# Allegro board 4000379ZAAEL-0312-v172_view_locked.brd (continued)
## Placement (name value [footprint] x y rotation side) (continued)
R937  4.7 K  [R0603]  62.29 85.85 180 top
R938  1 K/1%  [R0402]  131.32 21.11 270 top
R939  4.7 K  [R0603]  84.84 77.15 270 top
R940  4.7 K  [R0603]  104.46 101.54 90 top
R941  1 K/1%  [R0402]  132.46 21.11 90 top
R949  10 K  [R0402]  112.97 58.29 270 bottom
R951  49.9 OHM/1%  [R0402]  123.69 21.78 180 bottom
R955  22 OHM  [R0402]  138.05 50.61 180 top
R956  0 OHM  [R0402]  137.41 55.37 0 top
R958  10 K  [R0402]  137.67 49.21 90 top
R963  0 OHM  [R0402]  111.51 58.04 0 bottom
R975  0 OHM  [R0402]  114.68 58.1 180 bottom
R976  10 K/5%  [R0402]  133.77 51.09 90 top
R977  13 K/1%  [R0402]  133.77 49.19 90 top
R978  10 K/5%  [R0402]  133.77 55.38 90 top
R979  13 K/1%  [R0402]  133.77 53.48 90 top
R980  4.7 K  [R0603]  109.54 56.39 270 bottom
R983  16 K/1%  [R0402]  128.27 50.99 90 top
R984  20 K/1%  [R0402]  128.27 49.15 90 top
R985  220 K  [R0402]  34.54 149.92 180 top
R986  0 OHM  [R0402]  40.26 12.76 90 top
R987  0 OHM  [R0402]  35.12 12.76 90 top
R988  0 OHM  [R0402]  83.06 12.76 90 top
R989  0 OHM  [R0402]  77.98 12.76 90 top
R990  0 OHM  [R0402]  51.5 12.76 90 top
R991  0 OHM  [R0805]  29.21 152.27 0 top
R992  1 K  [R0402]  39.69 156.91 180 top
R993  0.01 OHM  [R1206]  39.69 158.62 180 top
R994  0.02 OHM  [R1206]  12.19 54.1 180 top
R995  68 K  [R0402]  36.39 149.92 0 top
R996  5.1 K  [R0402]  28.45 154.94 180 top
R997  5.1 K  [R0402]  30.29 154.94 0 top
R998  1.2 K  [R0402]  36.77 151.57 270 bottom
R999  10 K  [R0402]  36.77 154.31 270 bottom
R1000  0.01 OHM  [R1206]  12.19 56.39 180 top
R1001  0 OHM  [R0402]  45.53 12.83 90 top
R1002  0 OHM  [R0402]  57.15 12.76 90 top
R1003  0 OHM  [R0402]  62.36 12.76 90 top
R1004  0 OHM  [R0402]  67.63 12.76 90 top
R1005  0 OHM  [R0402]  72.83 12.83 90 top
R1007  51 K  [R0402]  27.05 68.96 90 top
R1008  453 K  [R0402]  27.05 67.06 90 top
R1009  9.31 K  [R0402]  30.35 70.61 0 top
R1011  4.7 OHM  [R1206]  6.99 55.5 90 top
R1012  120 K  [R0402]  28.07 71.63 180 top
R1013  10 K  [R0402]  28.07 70.61 180 top
R1014  0 OHM  [R1206]  51.5 114.11 270 top
R1015  0 OHM  [R1206]  18.54 148.46 90 top
R1016  0 OHM  [R1206]  16.26 148.46 90 top
R1017  22.1 OHM  [R0603]  40.7 128.91 180 bottom
R1018  47 OHM  [R0603]  40.51 128.71 180 top
R1019  0.5 OHM  [R1206]  45.34 127.51 270 bottom
R1020  0.5 OHM  [R1206]  44.32 131.83 180 bottom
R1021  22.1 OHM  [R0603]  40.7 131.44 180 bottom
R1022  47 OHM  [R0603]  43.12 130.75 180 top
R1023  22.1 OHM  [R0603]  40.89 138.94 0 bottom
R1024  47 OHM  [R0603]  43.12 139.45 0 top
R1025  0.5 OHM  [R1206]  44.32 138.49 180 bottom
R1026  0.5 OHM  [R1206]  36.26 139.89 270 bottom
R1027  22.1 OHM  [R0603]  38.04 141.22 90 bottom
R1028  47 OHM  [R0603]  37.97 141.22 90 top
R1029  4.7 K  [R1206]  16 66.67 180 top
R1030  4.7 K  [R1206]  16 68.96 180 top
R1031  4.7 K  [R1206]  16 71.25 180 top
R1032  100 OHM  [R1206]  18.92 109.6 180 top
R1033  499 K  [R0603]  34.42 105.03 180 top
R1034  0 OHM  [R0805]  136.91 27.84 180 top
R1035  0 OHM  [R0402]  133.41 28 270 top
R1036  0 OHM  [R0805]  130.18 24.16 0 top
R1037  0 OHM  [R0402]  135.76 21.11 90 top
R1038  200 K  [R0805]  37.15 104.39 0 bottom
R1039  20 OHM  [R0402]  28.89 157.29 90 top
R1040  20 OHM  [R0402]  29.84 157.29 90 top
R1041  0.5 OHM  [R1206]  34.04 139.89 270 bottom
R1042  0.5 OHM  [R1206]  44.32 136.27 180 bottom
R1043  0.5 OHM  [R1206]  43.12 127.51 270 bottom
R1044  0.5 OHM  [R1206]  44.32 134.05 180 bottom
R1045  4.99 K  [R0603]  11.94 52.2 180 top
R1046  200 K  [R0805]  37.91 106.87 270 bottom
R1047  9.76 K  [R0603]  37.27 102.74 180 bottom
R1048  4.7 K  [R0805]  35.43 98.3 90 top
R1049  1 K  [R0805]  34.67 95.82 180 top
RP1123  0 OHM  [R0805]  130.68 42.9 270 top
RP1124  0 OHM  [R1206]  131.04 31.43 90 top
RP1125  0 OHM  [R0805]  58.1 64.26 90 top
RP1126  0 OHM  [R1206]  63.56 83.06 270 top
RP1127  0 OHM  [R0805]  69.47 64.26 90 top
RP1128  0 OHM  [R1206]  81.98 78.42 180 top
RP1129  0 OHM  [R0805]  100.97 82.68 0 top
RP1130  0 OHM  [R1206]  101.23 100.09 180 top
RP1131  0 OHM  [R1206]  124.97 77.85 90 bottom
RP1132  0 OHM  [R1206]  53.53 84.33 90 top
RV1  SMBJ58A  [DOS-SMB-GRANDE]  46.8 120.84 90 top
RV39  ESDSLC0502P6  [VARS-DFN1610-6L-YANGJIE]  83.88 109.73 180 top
RV40  ESDSLC0502P6  [VARS-DFN1610-6L-YANGJIE]  79.69 109.73 180 top
RV41  ESDSLC0502P6  [VARS-DFN1610-6L-YANGJIE]  75.69 109.73 180 top
RV42  ESDSLC0502P6  [VARS-DFN1610-6L-YANGJIE]  71.75 109.73 180 top
RV52  BZ091N  [VARS-BZXXN]  75.44 149.73 180 top
RV53  BZ091N  [VARS-BZXXN]  72.01 153.8 180 top
RV54  BZ091N  [VARS-BZXXN]  68.58 149.73 180 top
RV55  BZ091N  [VARS-BZXXN]  65.15 153.8 180 top
RV56  BZ091N  [VARS-BZXXN]  125.35 149.73 180 top
RV57  BZ091N  [VARS-BZXXN]  122.05 153.8 180 top
RV58  BZ091N  [VARS-BZXXN]  118.49 149.73 180 top
RV59  BZ091N  [VARS-BZXXN]  115.06 153.8 180 top
RV60  BZ091N  [VARS-BZXXN]  92.08 149.73 180 top
RV61  BZ091N  [VARS-BZXXN]  88.65 153.8 180 top
RV62  BZ091N  [VARS-BZXXN]  85.22 149.73 180 top
RV63  BZ091N  [VARS-BZXXN]  81.79 153.8 180 top
RV64  BZ091N  [VARS-BZXXN]  108.71 149.73 180 top
RV65  BZ091N  [VARS-BZXXN]  101.85 149.73 180 top
RV66  BZ091N  [VARS-BZXXN]  105.28 153.8 180 top
RV67  BZ091N  [VARS-BZXXN]  98.42 153.8 180 top
SC84  0.1 UF/16V  [C0402]  119.13 77.15 270 bottom
SC85  0.1 UF/16V  [C0402]  120.08 77.15 270 bottom
SC129  10 UF/6.3V  [C0603]  108.78 86.23 90 top
SC130  0.1 UF/16V  [C0402]  121.28 78.3 270 bottom
SC131  1 UF 10V  [C0402]  117.47 87.63 90 top
SC133  10 UF/6.3V  [C0603]  124.59 82.99 270 top
SC134  1 UF 10V  [C0402]  119.57 81.66 270 bottom
SC135  0.1 UF/16V  [C0402]  124.84 84.61 0 bottom
SC136  10 UF/6.3V  [C0603]  120.35 84.89 180 top
SC138  0.1 UF/16V  [C0402]  114.87 84.9 270 top
SC141  0.1 UF/16V  [C0402]  124.82 83.64 0 bottom
SC147  0.1 UF/16V  [C0402]  113.22 89.34 90 top
SC148  0.1 UF/16V  [C0402]  110.68 84.58 180 top
SC149  1 UF 10V  [C0402]  115.25 94.87 90 top
SC150  0.1 UF/16V  [C0402]  111.44 89.34 90 top
SC151  10 UF/6.3V  [C0603]  112.08 81.79 270 top
SC152  1 UF 10V  [C0402]  112.65 83.57 0 top
SC153  0.1 UF/16V  [C0402]  117.1 83.19 225 bottom
SC157  0.1 UF/16V  [C0402]  96.99 87.33 90 bottom
SC158  5 PF/50V  [C0402]  109.28 87.95 180 bottom
SC163  5 PF/50V  [C0402]  109.28 88.9 180 bottom
SC164  33 PF/50V  [C0402]  129.98 88.07 90 top
SC165  33 PF/50V  [C0402]  129.98 86.17 270 top
SC168  5 PF/50V  [C0402]  116.69 84 270 top
SC214  0.1 UF/16V  [C0402]  113.03 84.9 270 top
SC215  22 UF/10V  [C0603]  110.74 81.79 270 top
SC216  22 UF/10V  [C0603]  114.68 98.36 90 top
SC218  0.1 UF/16V  [C0402]  118.05 96.65 0 top
SC219  1 UF 10V  [C0402]  118.05 97.6 0 top
SC235  5 PF/50V  [C0402]  108.65 96.14 270 bottom
SC236  5 PF/50V  [C0402]  127.38 91.69 270 bottom
SC239  5 PF/50V  [C0402]  109.28 88.9 180 top
SC240  5 PF/50V  [C0402]  107.51 87.95 0 top
SC242  0.1 UF/16V  [C0402]  129.29 93.98 180 bottom
SC246  5 PF/50V  [C0402]  108.65 90.81 90 bottom
SC247  5 PF/50V  [C0402]  108.65 94.36 90 bottom
SC248  5 PF/50V  [C0402]  108.71 86.8 0 bottom
SC249  5 PF/50V  [C0402]  127.38 93.54 270 bottom
SC250  5 PF/50V  [C0402]  107.15 84.48 0 bottom
SC251  5 PF/50V  [C0402]  100.58 96.77 180 bottom
SC252  5 PF/50V  [C0402]  107.12 85.41 0 bottom
SC253  5 PF/50V  [C0402]  108.65 92.58 90 bottom
SC254  4.7 UF/6.3V  [MLCC-0120X0070]  130.68 80.77 0 top
SC256  5 PF/50V  [C0402]  97.11 95.46 180 bottom
SC264  0.1 UF/16V  [C0402]  127.13 77.09 270 top
SC265  5 PF/50V  [C0402]  108.71 78.68 90 top
SC266  5 PF/50V  [C0402]  108.71 76.83 270 top
SC267  5 PF/50V  [C0402]  48.07 15.05 90 top
SC268  5 PF/50V  [C0402]  108.14 89.92 0 top
SC269  0.1 UF/16V  [C0402]  139.45 94.87 180 top
SC273  5 PF/50V  [C0402]  108.14 90.87 0 top
SC274  5 PF/50V  [C0402]  108.14 91.88 0 top
SC275  5 PF/50V  [C0402]  108.14 92.84 0 top
SC435  5 PF/50V  [C0402]  126.43 95.31 270 bottom
SC446  0.1 UF/16V  [C0402]  112.78 90.74 180 top
SC447  0.1 UF/16V  [C0402]  112.84 92.27 270 top
SC448  10 UF/6.3V  [C0603]  116.78 93.22 270 top
SC449  0.1 UF/16V  [C0402]  113.98 84.9 270 top
SC465  0.1 UF/16V  [C0402]  123.25 94.11 90 top
SC466  0.1 UF/16V  [C0402]  119.89 98.17 0 top
SC467  10 UF/6.3V  [C0603]  125.73 94.68 90 top
SC469  0.1 UF/16V  [C0402]  118.17 85.61 180 top
SC470  0.1 UF/16V  [C0402]  123.34 86.72 0 top
SC472  0.1 UF/16V  [C0402]  122.81 90.87 0 top
SC473  0.1 UF/16V  [C0402]  123.25 92.33 270 top
SC474  0.1 UF/16V  [C0402]  122.36 92.33 270 top
SC475  0.1 UF/16V  [C0402]  122.36 94.11 90 top
SC476  0.1 UF/16V  [C0402]  113.03 94.74 90 top
SC477  0.1 UF/16V  [C0402]  112.08 94.74 90 top
SC478  10 UF/6.3V  [C0603]  123.25 82.99 270 top
SC479  10 UF/6.3V  [C0603]  124.4 94.68 90 top
SC484  0.1 UF/16V  [C0402]  120.78 88.39 270 top
SC485  100 PF/50V  [C0201]  122.43 98.17 0 top
SC486  0.1 UF/16V  [C0402]  115.25 96.27 180 top
SC488  1 UF 10V  [C0402]  120.78 90.17 90 top
SC489  0.1 UF/16V  [C0402]  119.89 92.84 270 top
SC490  0.1 UF/16V  [C0402]  111.89 92.27 270 top
SC492  0.1 UF/16V  [C0402]  111.12 94.74 90 top
SC493  0.1 UF/16V  [C0402]  122.17 88.84 90 top
SC494  0.1 UF/16V  [C0402]  118.94 92.84 270 top
SC495  0.1 UF/16V  [C0402]  115.63 92.9 270 top
SC496  0.1 UF/16V  [C0402]  114.68 92.9 270 top
SC499  5 PF/50V  [C0402]  103.25 81.66 270 bottom
SC500  5 PF/50V  [C0402]  107.06 81.66 270 bottom
SC501  5 PF/50V  [C0402]  109.92 81.66 270 bottom
SC502  5 PF/50V  [C0402]  112.78 81.66 270 bottom
SC504  47 UF/6.3V  [C0805]  106.49 85.92 90 top
SC506  22 UF/10V  [C0603]  109.92 94.74 90 top
SC509  47 UF/6.3V  [C0805]  122.81 77.85 270 bottom
SC510  47 UF/6.3V  [C0805]  122.43 96.9 0 top
SC512  47 UF/6.3V  [C0805]  125.86 91.85 270 top
SC513  47 UF/6.3V  [C0805]  113.03 98.49 90 top
SC514  47 UF/6.3V  [C0805]  126.17 82.87 270 top
SC515  1 PF/50V  [C0402]  123.13 88.84 90 top
SC517  1 PF/50V  [C0402]  118.17 84.72 180 top
SC518  0.1 UF/16V  [C0402]  114.68 89.41 90 top
SC519  0.1 UF/16V  [C0402]  112.33 89.34 90 top
SC520  330 PF/50V  [C0402]  139.89 91.88 90 top
SC521  330 PF/50V  [C0402]  139.89 90.04 270 top
SC523  5 PF/50V  [C0402]  99.49 85.39 180 bottom
SC600  BOB TOP COVER  [SHIELD-COVER]  47.65 21.48 270 top
SC601  BOB BOTTOM COVER  [SHIELD-COVER]  61.76 19.09 90 bottom
SC602  SHIELDING COVER  [SHIELD-COVER]  74.17 82.42 0 top
SD2  SCS4148LWS-C  [DOS-SOD-323L-SECOS]  128.4 78.87 90 top
SF600  BOB TOP FRAME  [SHIELD-05460X02020-0995]  41.87 31.45 90 top
SF601  BOB BOTTOM FRAME  [SHIELD-04430X02373-TEST]  47.02 29.37 90 bottom
SF602  SHIELDING FRAME  [SHIELD-02340X02320-0300-1]  77.72 94.11 180 top
SF603  SHIELDING FRAME  [SHIELD-04250X03180-0200-1]  115.57 89.92 0 top
SF604  SHIELDING FRAME  [SHIELD-04250X03180-0200-1]  115.57 89.92 180 bottom
SL17  PBY100505T-121Y-N  [FILTS-0402]  116.27 97.6 0 top
SL29  PBY100505T-121Y-N  [FILTS-0402]  122.1 84.28 90 top
SR39  4.7 K  [R0402]  105.28 88.06 180 bottom
SR40  4.7 K  [R0402]  107.7 92.58 90 bottom
SR41  4.7 K  [R0402]  106.24 92.9 180 bottom
SR42  4.7 K  [R0402]  107.51 88.9 0 bottom
SR43  4.7 K  [R0402]  105.28 89 180 bottom
SR49  4.7 K  [R0402]  106.3 94.74 180 bottom
SR50  4.7 K  [R0402]  126.43 93.54 270 bottom
SR51  4.7 K  [R0402]  129.29 93.09 0 bottom
SR56  4.7 K  [R0402]  129.29 94.87 0 bottom
SR57  1.5 K  [R0402]  107.31 76.33 0 top
SR58  4.7 K  [R0402]  106.3 95.69 180 bottom
SR62  1.5 K  [R0402]  115.7 77.15 270 bottom
SR63  1.5 K  [R0402]  115.82 86.74 270 top
SR64  1.5 K  [R0402]  105.92 78.61 90 top
SR65  1.5 K  [R0402]  105.92 80.39 90 top
SR67  1.5 K  [R0402]  105.92 76.83 270 top
SR69  33 OHM  [R0402]  107.31 78.23 0 top
SR70  33 OHM  [R0402]  107.31 77.28 0 top
SR71  4.7 K  [R0402]  105.28 88.9 180 top
SR72  4.7 K  [R0402]  120.24 86.11 180 top
SR73  4.7 K  [R0402]  120.08 87.06 0 top
SR74  4.7 K  [R0402]  109.28 87.95 180 top
SR75  4.7 K  [R0402]  107.7 94.36 90 bottom
SR76  4.7 K  [R0402]  105.28 87.95 180 top
SR78  1M OHM  [R1206]  128.33 87.31 270 top
SR79  4.7 K  [R0402]  107.7 90.81 90 bottom
SR80  10 K  [R0402]  97.09 92.65 0 bottom
SR81  10 K  [R0402]  99.49 84.45 0 bottom
SR82  10 K  [R0402]  103.95 84.07 90 bottom
SR84  10 K  [R0402]  97.09 90.68 0 bottom
SR85  10 K  [R0402]  103.95 85.85 270 bottom
SR87  1 K  [R0402]  97.09 89.66 180 bottom
SR88  47 K  [R0402]  127.13 79.63 90 top
SR89  1 K  [R0402]  123.19 81.66 90 bottom
SR90  4.7 K  [R0402]  126.11 79.63 90 top
SR91  1 K  [R0402]  122.3 81.66 90 bottom
SR93  1 K  [R0402]  121.41 81.66 90 bottom
SR94  1 K  [R0402]  120.52 81.66 90 bottom
SR96  4.7 K  [R0402]  106.3 91.25 180 bottom
SR98  10 K  [R0402]  97.09 91.63 0 bottom
SR119  4.7 K  [R0402]  126.43 91.69 270 bottom
SR124  4.7 K  [R0402]  127.38 95.31 270 bottom
SR127  4.7 K  [R0402]  129.29 91.44 0 bottom
SR128  33 OHM  [R0402]  116.26 85.37 180 top
SR129  4.7 K  [R0402]  107.51 88.9 0 top
SR132  4.7 K  [R0402]  107.7 96.14 270 bottom
SR133  4.7 K  [R0402]  107.51 87.95 0 bottom
SR136  33 OHM  [R0402]  126.94 87 180 bottom
SR138  33 OHM  [R0402]  126.94 87.95 180 bottom
SR139  33 OHM  [R0402]  100.58 95.82 0 bottom
SR140  33 OHM  [R0402]  105.37 84.48 0 bottom
SR141  33 OHM  [R0402]  105.35 85.41 0 bottom
SR142  33 OHM  [R0402]  97.56 94.06 90 bottom
SR143  0 OHM  [R0402]  124.71 80.01 180 top
SR153  1.5 K  [R0402]  138.94 90.04 90 top
SR157  1.5 K  [R0402]  138.94 91.88 270 top
SR158  33 OHM  [R0402]  126.94 89.85 0 bottom
SR159  33 OHM  [R0402]  126.94 88.9 0 bottom
SR175  33 OHM  [R0402]  106.63 86.97 180 bottom
SR259  0 OHM  [R0402]  118.05 77.15 270 bottom
SR260  0 OHM  [R0402]  117.09 77.15 270 bottom
SR390  33 OHM  [R0402]  112.78 77.15 270 bottom
SR422  0 OHM  [R0402]  126.17 86.68 180 top
SR423  0 OHM  [R0402]  126.17 87.57 180 top
SR485  2.49 K  [R0402]  118.3 94.74 0 top
SR536  4.7 K  [R0402]  124.14 91.44 270 top
SR603  33 OHM  [R0402]  110.87 81.66 90 bottom
SR604  33 OHM  [R0402]  108.01 81.66 90 bottom
SR605  33 OHM  [R0402]  105.16 81.66 90 bottom
SR606  33 OHM  [R0402]  102.3 81.66 90 bottom
SR607  33 OHM  [R0402]  110.68 59.05 90 top
SR608  33 OHM  [R0402]  109.73 59.05 90 top
SR609  33 OHM  [R0402]  114.74 77.15 90 bottom
SR610  33 OHM  [R0402]  113.79 77.15 90 bottom
SR611  1.5 K  [R0402]  111.82 81.66 90 bottom
SR612  1.5 K  [R0402]  108.97 81.66 90 bottom
SR613  1.5 K  [R0402]  106.11 81.66 90 bottom
SR614  1.5 K  [R0402]  104.2 81.66 90 bottom
SW800  KAN0631-0501B  [SW-KAN0631-0501B]  48.69 165.75 180 top
SY3  S3225A-025000-T20-DDS-1AMA  [XTALS-0320X0250-YOKE]  132.67 87.59 180 top
T1  UTTG24C02P  [TRS24-UTTG24CXX]  77.09 121.79 0 top
T2  UTG24C01P  [TRS24-UTG24C]  128.27 121.79 0 top
T5  PL9954-001SR  [TRS12-PL9954]  19.05 91.44 0 top
T17  UTV48C01P  [TRS48-UTV48C]  103.26 121.77 0 top
TP1  TP  [TP13]  110.26 48.18 180 bottom
TP2  TP  [TP13]  70.17 100.97 0 top
TP3  TP  [TP13]  70.23 98.17 0 top
TP4  TP  [TP13]  71.56 101.09 0 top
TP5  TP  [TP13]  29.46 15.49 0 top
TP6  TP  [TP13]  111.06 57.66 0 top
TP7  TP  [TP13]  100.14 56.64 0 top
TP8  TP  [TP13]  97.66 57.02 0 top
TP9  TP  [TP13]  96.08 53.09 0 top
TP10  TP  [TP13]  105.28 87.12 180 bottom
TP11  TP  [TP13]  45.15 15.49 90 top
TP12  TP  [TP13]  110.74 90.42 180 bottom
TP13  TP  [TP13]  51.5 15.49 0 top
TP14  TP  [TP13]  56.71 15.49 0 top
TP15  TP  [TP13]  61.91 15.49 0 top
TP16  TP  [TP13]  67.25 15.56 0 top
TP17  TP  [TP13]  114.74 75.76 180 bottom
TP18  TP  [TP13]  113.79 75.76 0 bottom
TP19  TP  [TP13]  128.33 87.95 180 bottom
TP20  TP  [TP13]  128.4 87 180 bottom
TP21  TP  [TP13]  109.41 84.77 180 bottom
TP22  TP  [TP13]  108.65 85.53 180 bottom
TP23  TP  [TP13]  102.17 96.65 180 bottom
TP24  TP  [TP13]  97.54 96.46 180 bottom
TP25  TP  [TP13]  96.96 85.92 180 bottom
TP26  TP  [TP13]  110.87 80.2 180 bottom
TP27  TP  [TP13]  108.01 80.2 180 bottom
TP28  TP  [TP13]  105.16 80.26 180 bottom
TP29  TP  [TP13]  102.3 80.26 180 bottom
TP30  TP  [TP13]  84.99 43.33 0 top
TP31  TP  [TP13]  120.4 91.44 0 top
TP32  TP  [TP13]  119.44 91.44 0 top
TP33  TP  [TP13]  96.52 56.77 0 top
TP34  TP  [TP13]  96.52 55.88 0 top
U1  PRX321  [BGA296-29X28-INTEL]  104.46 49.84 180 top
U5  M24C32-WMN6TP  [SOP8-0600-1270]  101.54 78.74 270 top
U7  MX25L1606EM2I-12G  [SOP8-0790-1270]  100.8 90.64 0 bottom
U12  W632GU6NB-09  [BGA96-16X9-08000350-RM]  114.53 21.19 180 top
U13  W632GU6NB-09  [BGA96-16X9-08000350-RM]  94.16 21.19 180 top
U18  W25N01GVZEIG  [SON8-0800-1270-VIA-3]  78.42 44.96 180 top
U22  TPT72617-SO1R  [SOP8-0600-1270]  24.51 139.38 180 top
U27  JD6621W7  [QFN20-0400-0500-VIA-30]  34.92 153.1 180 top
U39  LTV-217-B-G  [SOP4-0700-1270]  34.8 89.98 180 top
U66  RTL8366U-CG  [QFN144-1100-0500-PAD]  117.7 90.11 0 bottom
U108  AIC809-29GUTR  [SOT-23-RGV]  131.19 78.23 180 top
U601  GN28L98  [QFN32-0400-0400-VIA-5-PH10]  60.56 34.99 180 top
U602  PLDM588-428  [OPTIC-THBD277E4S]  52.66 27.04 180 top
U604  FM24C08D-TS-T-G  [SOP8-0640-0650]  43.21 25.13 90 bottom
U904  TPL51206-DFFR  [SON10-0200-0400-VIA-1]  134.87 24.09 270 top
U909  TPS23861PWR  [SOP28-0640-0650-3]  36.2 135.57 0 top
USB1  PU-59-3221-31002-5  [CONS24-31862-024XX-001]  32.47 167.17 180 top
Y3  7M40090021  [XTALS-0320X0250-3]  87.44 48.51 45 top

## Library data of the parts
C1 C2 C9-C29 C94-C96 C98-C106 C110-C117 C136 C137 C139-C146 C148 C151 C156 C159-C162 C166-C239 C241-C267 C272 C276-C286 C288 C293 C294 C602 C603 C606-C608 C611-C614 C616 C619-C621 C623-C626 C631-C640 C643 C644 C719 C720 C810 C843-C852 C911 C922 C925-C928 C944 C946-C949 C956-C961 C971-C974 C976-C981 C1002-C1014 C8557-C8562 C8564-C8568 C8571-C8578 C8580-C8583 C8595 C8596 CE19-CE38 CE72-CE81 E1C1 E1C2 E1C14 E1C16 E1C21-E1C24 E1C29-E1C100 E1C149-E1C152 EC16-EC22 EC300 EC301 EC340 PC351-PC407 PC430 PC484-PC487 PC677 PC679-PC691 SC129-SC131 SC133-SC136 SC138 SC141 SC147-SC153 SC157 SC158 SC163-SC165 SC168 SC214-SC216 SC218 SC219 SC235 SC236 SC239 SC240 SC242 SC246-SC254 SC256 SC264-SC269 SC273-SC275 SC435 SC446-SC449 SC465-SC467 SC469 SC470 SC472-SC479 SC484-SC486 SC488-SC490 SC492-SC496 SC499-SC502 SC504 SC506 SC509 SC510 SC512-SC515 SC517-SC521 SC523 = CAP-NP
C86 C87 C89 C93 SC84 SC85 = CAP-NP: signal model: CAP-NP_C0402_0.1_UF/16V_0.1_UF/16V
C153-C155 = CAP-NP: room: DDR0_L
C270 C271 C600 C601 C609 C610 EC334 EC335 = CAP-NP: signal model: CAP-NP_C0201_0.1_UF/10V_0.1_UF/10V
C8569 C8584-C8586 = CAP
D3 D600 D601 D807 D808 D815 D816 SD2 = DIODE_1
D65-D108 D111-D126 D809 D811 D813 D814 D903 D904 = VAR-2PIN
D109 D110 D127 D128 = VAR-2PIN_0
D802-D806 D810 D822-D825 = LED-2PIN
D812 D819-D821 = SCHOTTKY DIODES
D817 = ZENER DIODE
D818 = DIODE_1-REF
E1FB1 E1L2 E1L3 E1L5 E1L6 E1LP1 = FERRITE_BEAD
E1L1 E1L4 = CHOKE_POWER
E1R1-E1R3 E1R5 E1R12-E1R15 E1R20 E1R22 E1R24-E1R31 ER331 L604 L606 L607 L611 L612 PR113 PR337-PR356 PR380 PR383 PR386-PR388 PR460-PR471 PR607-PR615 PR619 R27 R28 R66 R68 R83 R89 R91 R93 R94 R105-R116 R118-R128 R130-R133 R135 R136 R151 R152 R154-R156 R172-R200 R203 R229-R235 R239-R258 R261 R274 R277 R278 R350-R353 R357 R358 R495-R502 R604-R606 R610 R613 R614 R617 R620 R621 R623 R629 R630 R633 R635-R639 R641 R642 R644 R647 R648 R651 R652 R655 R656 R660 R662 R664 R665 R699 R800-R811 R830-R839 R905 R916 R918 R928 R936-R941 R949 R951 R955 R956 R958 R963 R975-R978 R980 R983-R992 R995-R999 R1001-R1005 R1007-R1009 R1011-R1049 RP1123-RP1132 SR39-SR43 SR49-SR51 SR56-SR58 SR62-SR65 SR67 SR69-SR76 SR78-SR82 SR84 SR85 SR87-SR91 SR93 SR94 SR96 SR98 SR119 SR124 SR127-SR129 SR132 SR133 SR136 SR138-SR143 SR153 SR157-SR159 SR175 SR390 SR422 SR423 SR485 SR536 SR603-SR614 = RESISTOR
E1U1 = RTL8261BE_SYMBOL_STANDARD_0
ER359 ER360 R611 R612 R615 R616 SR259 SR260 = RESISTOR: signal model: RESISTOR_R0402_0_OHM_0_OHM
EY300 SY3 = XTAL-4P_0
F1-F4 = FUSE-2PIN
FB5-FB10 FB12 FB13 FB15 L65 L600-L603 L605 L912 PL180-PL183 PL333 PL353 SL17 SL29 = INDUCTOR
FB14 = BLM15HG102SN1
H01 H02 H03 H04 = 1-PIN
J1 = DEBUG_UART_0
J7 = CON-1X4-R
P3-P6 = RJ-45-8P_0
PU10 = MP2329GG-Z_5
PU14-PU17 = MP1657GTF-Z_9
PU23 = RT7297AHZSP_5
PU30 = MP4541GN_2
PU40 = MP2329GG-Z_11
PU902 = RT9193-18PB_2
PU908 = RT9193-18PB_3
Q1-Q10 Q808 = TRANSISTOR-NPN-EBC
Q600 Q602 Q803 = POWERMOSFET-N
Q601 Q603 = BC856BDW1T1G
Q802 = MOSFET-N -8PIN
Q804-Q807 = SI4850EY
R979 R993 R994 R1000 = Resistor-2
RV1 = ZENER-DIODE
RV39-RV42 = VAR-2PIN_4
RV52 = VAR_0
RV53 = VAR_1
RV54 = VAR_2
RV55 = VAR_3
RV56 RV60 RV64 = VAR_4
RV57 RV61 RV66 = VAR_5
RV58 RV62 RV65 = VAR_6
RV59 RV63 RV67 = VAR_7
SC600 SC602 = 41-SP00-4211G1A1002_0
SC601 = SHIELD-COVER
SF600 = 3PIN-123
SF601 = 2-PIN
SF602 = 3PIN-123_1
SF603 SF604 = 2-PIN_0
SW800 = SW21-34G
T1 T2 = TRANSFORMER-24-1PIN_0
T5 = TG-UT38940S_3
T17 = TRS-48PIN
TP1-TP34 = TP_0
U1 = PRX120_12
U5 = M24C32
U7 = MX25L8006
U12 = SDRAM-DDR3-64M16-BGA96-ALT_7
U13 = SDRAM-DDR3-64M16-BGA96-ALT_6
U18 = MT29F2G01ABAGDWB_5
U22 = ISO1541
U27 = MP2329GG-Z_3
U39 = LTV-817A
U66 = RTL8366U_0
U108 = AIC809-29GUTR
U601 = GN28L95_2
U602 = 10G_BOSA_Tx&Rx_Flex_Hisense_2
U604 = FM24C08D-TS-T-G
U904 = TPL51206_0
U909 = TLV62095_6
USB1 = USB-TYPE-C_1
Y3 = XTAL-4P

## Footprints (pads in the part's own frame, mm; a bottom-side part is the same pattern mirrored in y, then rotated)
BGA96-16X9-08000350-RM
  round 0.356 smd: A1(-3.2,6) A2(-2.4,6) A3(-1.6,6) A7(1.6,6) A8(2.4,6) A9(3.2,6) B1(-3.2,5.2) B2(-2.4,5.2) B3(-1.6,5.2) B7(1.6,5.2) B8(2.4,5.2) B9(3.2,5.2) C1(-3.2,4.4) C2(-2.4,4.4) C3(-1.6,4.4) C7(1.6,4.4) C8(2.4,4.4) C9(3.2,4.4) D1(-3.2,3.6) D2(-2.4,3.6) D3(-1.6,3.6) D7(1.6,3.6) D8(2.4,3.6) D9(3.2,3.6) E1(-3.2,2.8) E2(-2.4,2.8) E3(-1.6,2.8) E7(1.6,2.8) E8(2.4,2.8) E9(3.2,2.8) F1(-3.2,2) F2(-2.4,2) F3(-1.6,2) F7(1.6,2) F8(2.4,2) F9(3.2,2) G1(-3.2,1.2) G2(-2.4,1.2) G3(-1.6,1.2) G7(1.6,1.2) G8(2.4,1.2) G9(3.2,1.2) H1(-3.2,0.4) H2(-2.4,0.4) H3(-1.6,0.4) H7(1.6,0.4) H8(2.4,0.4) H9(3.2,0.4) J1(-3.2,-0.4) J2(-2.4,-0.4) J3(-1.6,-0.4) J7(1.6,-0.4) J8(2.4,-0.4) J9(3.2,-0.4) K1(-3.2,-1.2) K2(-2.4,-1.2) K3(-1.6,-1.2) K7(1.6,-1.2) K8(2.4,-1.2) K9(3.2,-1.2) L1(-3.2,-2) L2(-2.4,-2) L3(-1.6,-2) L7(1.6,-2) L8(2.4,-2) L9(3.2,-2) M1(-3.2,-2.8) M2(-2.4,-2.8) M3(-1.6,-2.8) M7(1.6,-2.8) M8(2.4,-2.8) M9(3.2,-2.8) N1(-3.2,-3.6) N2(-2.4,-3.6) N3(-1.6,-3.6) N7(1.6,-3.6) N8(2.4,-3.6) N9(3.2,-3.6) P1(-3.2,-4.4) P2(-2.4,-4.4) P3(-1.6,-4.4) P7(1.6,-4.4) P8(2.4,-4.4) P9(3.2,-4.4) R1(-3.2,-5.2) R2(-2.4,-5.2) R3(-1.6,-5.2) R7(1.6,-5.2) R8(2.4,-5.2) R9(3.2,-5.2) T1(-3.2,-6) T2(-2.4,-6) T3(-1.6,-6) T7(1.6,-6) T8(2.4,-6) T9(3.2,-6)
BGA296-29X28-INTEL
  round 0.356 smd: A2(-5.454,5.75) A28(5.454,5.75) AG1(-5.95,-5.254) AG29(5.95,-5.254) AH2(-5.454,-5.75) AH28(5.454,-5.75) B1(-5.95,5.254) B29(5.95,5.254)
  round 0.305 smd: A4(-4.754,5.75) A6(-4.079,5.75) A25(4.079,5.75) A26(4.754,5.75) AA2(-5.544,-2.692) AA4(-4.707,-2.692) AA6(-4.064,-2.845) AA8(-3.251,-2.845) AA10(-2.438,-2.845) AA12(-1.626,-2.845) AA14(-0.813,-2.845) AA16(0,-2.845) AA18(0.813,-2.845) AA20(1.626,-2.845) AA22(2.438,-2.845) AA24(3.251,-2.845) AA25(4.064,-2.845) AA26(4.707,-2.692) AA28(5.544,-2.692) AB3(-5.113,-3.124) AB27(5.113,-3.124) AC2(-5.372,-3.726) AC4(-4.656,-3.543) AC6(-4.064,-3.658) AC8(-3.251,-3.658) AC10(-2.438,-3.658) AC12(-1.626,-3.658) AC14(-0.813,-3.658) AC16(0,-3.658) AC18(0.813,-3.658) AC20(1.626,-3.658) AC22(2.438,-3.658) AC24(3.251,-3.658) AC25(4.064,-3.658) AC26(4.656,-3.543) AC28(5.372,-3.726) AD1(-5.95,-3.861) AD4(-4.904,-4.093) AD27(4.904,-4.093) AD29(5.95,-3.861) AE1(-5.95,-4.554) AE2(-5.353,-4.482) AE7(-3.338,-4.507) AE10(-2.474,-4.507) AE12(-1.61,-4.507) AE14(-0.747,-4.507) AE16(0.117,-4.507) AE18(0.98,-4.507) AE20(1.844,-4.507) AE22(2.708,-4.507) AE24(3.571,-4.507) AE26(4.537,-4.576) AE28(5.353,-4.482) AE29(5.95,-4.554) AF5(-4.319,-4.675) AF6(-3.769,-4.913) AF9(-2.906,-4.913) AF11(-2.042,-4.913) AF13(-1.179,-4.913) AF15(-0.315,-4.913) AF17(0.549,-4.913) AF19(1.412,-4.913) AF21(2.276,-4.913) AF23(3.139,-4.913) AG3(-5.274,-5.074) AG4(-4.682,-5.153) AG7(-3.338,-5.344) AG10(-2.474,-5.344) AG12(-1.61,-5.344) AG14(-0.747,-5.344) AG16(0.117,-5.344) AG18(0.98,-5.344) AG20(1.844,-5.344) AG22(2.708,-5.344) AG24(3.571,-5.344) AG25(4.072,-5.023) AG26(4.682,-5.153) AG28(5.274,-5.074) AH4(-4.754,-5.75) AH6(-4.079,-5.75) AH25(4.079,-5.75) AH26(4.754,-5.75) B4(-4.682,5.153) B7(-3.338,5.344) B10(-2.474,5.344) B12(-1.61,5.344) B14(-0.747,5.344) B16(0.117,5.344) B18(0.98,5.344) B20(1.844,5.344) B22(2.708,5.344) B24(3.571,5.344) B26(4.682,5.153) C3(-5.274,5.074) C6(-3.769,4.913) C9(-2.906,4.913) C11(-2.042,4.913) C13(-1.179,4.913) C15(-0.315,4.913) C17(0.549,4.913) C19(1.412,4.913) C21(2.276,4.913) C23(3.139,4.913) C25(4.072,5.023) C28(5.274,5.074) D1(-5.95,4.554) D2(-5.353,4.482) D5(-4.319,4.675) D7(-3.338,4.507) D10(-2.474,4.507) D12(-1.61,4.507) D14(-0.747,4.507) D16(0.117,4.507) D18(0.98,4.507) D20(1.844,4.507) D22(2.708,4.507) D24(3.571,4.507) D25(4.18,4.44) D28(5.353,4.482) D29(5.95,4.554) E4(-4.569,4.036) E26(4.599,4) F1(-5.95,3.861) F3(-5.113,3.785) F6(-4.064,3.658) F8(-3.251,3.658) F10(-2.438,3.658) F12(-1.626,3.658) F14(-0.813,3.658) F16(0,3.658) F18(0.813,3.658) F20(1.626,3.658) F22(2.438,3.658) F24(3.251,3.658) F25(4.064,3.658) F27(5.184,3.9) F29(5.95,3.861) G2(-5.544,3.353) G4(-4.707,3.353) G26(4.707,3.353) G28(5.544,3.353) H3(-5.113,2.921) H6(-4.064,2.845) H8(-3.251,2.845) H10(-2.438,2.845) H12(-1.626,2.845) H14(-0.813,2.845) H16(0,2.845) H18(0.813,2.845) H20(1.626,2.845) H22(2.438,2.845) H24(3.251,2.845) H25(4.064,2.845) H27(5.113,2.921) J2(-5.544,2.489) J4(-4.707,2.489) J26(4.707,2.489) J28(5.544,2.489) K3(-5.113,2.057) K6(-4.064,2.032) K8(-3.251,2.032) K10(-2.438,2.032) K12(-1.626,2.032) K14(-0.813,2.032) K16(0,2.032) K18(0.813,2.032) K20(1.626,2.032) K22(2.438,2.032) K24(3.251,2.032) K25(4.064,2.032) K27(5.113,2.057) L2(-5.544,1.626) L4(-4.707,1.626) L26(4.707,1.626) L28(5.544,1.626) M3(-5.113,1.194) M6(-4.064,1.219) M8(-3.251,1.219) M10(-2.438,1.219) M12(-1.626,1.219) M14(-0.813,1.219) M16(0,1.219) M18(0.813,1.219) M20(1.626,1.219) M22(2.438,1.219) M24(3.251,1.219) M25(4.064,1.219) M27(5.113,1.194) N2(-5.544,0.762) N4(-4.707,0.762) N26(4.707,0.762) N28(5.544,0.762) P3(-5.113,0.33) P6(-4.064,0.406) P8(-3.251,0.406) P10(-2.438,0.406) P12(-1.626,0.406) P14(-0.813,0.406) P16(0,0.406) P18(0.813,0.406) P20(1.626,0.406) P22(2.438,0.406) P24(3.251,0.406) P25(4.064,0.406) P27(5.113,0.33) R2(-5.544,-0.102) R4(-4.707,-0.102) R26(4.707,-0.102) R28(5.544,-0.102) T3(-5.113,-0.533) T6(-4.064,-0.406) T8(-3.251,-0.406) T10(-2.438,-0.406) T12(-1.626,-0.406) T14(-0.813,-0.406) T16(0,-0.406) T18(0.813,-0.406) T20(1.626,-0.406) T22(2.438,-0.406) T24(3.251,-0.406) T25(4.064,-0.406) T27(5.113,-0.533) U2(-5.544,-0.965) U4(-4.707,-0.965) U6(-4.064,-1.219) U8(-3.251,-1.219) U10(-2.438,-1.219) U12(-1.626,-1.219) U14(-0.813,-1.219) U16(0,-1.219) U18(0.813,-1.219) U20(1.626,-1.219) U22(2.438,-1.219) U24(3.251,-1.219) U25(4.064,-1.219) U26(4.707,-0.965) U28(5.544,-0.965) V3(-5.113,-1.397) V27(5.113,-1.397) W2(-5.544,-1.829) W4(-4.707,-1.829) W6(-4.064,-2.032) W8(-3.251,-2.032) W10(-2.438,-2.032) W12(-1.626,-2.032) W14(-0.813,-2.032) W16(0,-2.032) W18(0.813,-2.032) W20(1.626,-2.032) W22(2.438,-2.032) W24(3.251,-2.032) W25(4.064,-2.032) W26(4.707,-1.829) W28(5.544,-1.829) Y3(-5.113,-2.261) Y27(5.113,-2.261)
  oval 0.152x0.254 smd: A9(-2.906,5.75) A11(-2.042,5.75) A13(-1.179,5.75) A15(-0.315,5.75) A17(0.549,5.75) A19(1.412,5.75) A21(2.276,5.75) A23(3.139,5.75) AH9(-2.906,-5.75) AH11(-2.042,-5.75) AH13(-1.179,-5.75) AH15(-0.315,-5.75) AH17(0.549,-5.75) AH19(1.412,-5.75) AH21(2.276,-5.75) AH23(3.139,-5.75)
  oval 0.254x0.152 smd: AB1(-5.95,-3.124) AB29(5.95,-3.124) H1(-5.95,2.921) H29(5.95,2.921) K1(-5.95,2.057) K29(5.95,2.057) M1(-5.95,1.194) M29(5.95,1.194) P1(-5.95,0.33) P29(5.95,0.33) T1(-5.95,-0.533) T29(5.95,-0.533) V1(-5.95,-1.397) V29(5.95,-1.397) Y1(-5.95,-2.261) Y29(5.95,-2.261)
C0201
  rect 0.305x0.305 smd: 1(-0.246,0) 2(0.246,0)
C0402
  rect 0.508x0.508 smd: 1(-0.429,0) 2(0.429,0)
C0603
  custom 0.222x0.222 smd: 1(-0.681,0) 2(0.681,0)
C0805
  rect 0.991x1.397 smd: 1(-0.795,0) 2(0.795,0)
C1206
  custom 0.384x0.384 smd: 1(-1.212,0) 2(1.212,0)
C1206-0160
  rect 1.27x1.6 smd: 1(-1.463,0) 2(1.463,0)
C1210
  rect 1.6x2.692 smd: 1(-1.39,0) 2(1.39,0)
CES-1250-P-1350-L
  rect 5.994x3.2 smd: 1(-5,0) 2(5,0)
CES-1800-P-1750-S
  rect 7.696x5.004 smd: 1(-7.15,0) 2(7.15,0)
CONS24-31862-024XX-001
  round 0.61 hole 0.61 unplated: (-3.6,1.65)
  oval 0.864x0.508 hole 0.864x0.508 unplated: (3.6,1.715)
  oval 1.194x2.311 hole 0.61x1.905: 25(-4.32,3.65) 26(4.32,3.65)
  oval 1.448x1.092 hole 1.27x0.711: 27(-3.995,3.05) 28(3.995,3.05)
  oval 1.295x2.591 hole 0.711x2.007: 29(-4.32,-1.4) 30(4.32,-1.4)
  rect 0.279x0.889 smd: A1(-2.625,4.35) A2(-2.125,4.35) A3(-1.625,4.35) A4(-1.125,4.35) A5(-0.625,4.35) A6(-0.125,4.35) A7(0.375,4.35) A8(0.875,4.35) A9(1.375,4.35) A10(1.875,4.35) A11(2.375,4.35) A12(2.875,4.35)
  rect 0.279x0.787 smd: B1(2.625,2.75) B2(2.125,2.75) B3(1.625,2.75) B4(1.125,2.75) B5(0.625,2.75) B6(0.125,2.75) B7(-0.375,2.75) B8(-0.875,2.75) B9(-1.375,2.75) B10(-1.875,2.75) B11(-2.375,2.75) B12(-2.875,2.75)
DOS-SMA-FL-LRC
  rect 1.6x1.778 smd: A(1.85,0) C(-1.85,0)
DOS-SMA-PANJIT
  rect 2.057x2.057 smd: A(1.865,0) C(-1.865,0)
DOS-SMB-GRANDE
  rect 2.108x2.388 smd: A(2.35,0) C(-2.35,0)
DOS-SOD-123-PANJIT
  rect 0.965x1.219 smd: A(1.64,0) C(-1.64,0)
DOS-SOD-123HE-PANJIT
  rect 1.295x1.397 smd: A(1.55,0)
  rect 2.591x1.397 smd: C(-0.9,0)
DOS-SOD-323-GRANDE
  rect 0.737x0.508 smd: A(1.085,0) C(-1.085,0)
DOS-SOD-323-PANJIT
  rect 0.559x0.813 smd: A(1.155,0) C(-1.155,0)
DOS-SOD-323-WILLAS
  rect 0.711x0.838 smd: A(1.075,0) C(-1.075,0)
DOS-SOD-323L-SECOS
  rect 0.787x0.787 smd: A(1.1,0) C(-1.1,0)
FILTS-0402
  rect 0.508x0.508 smd: 1(-0.429,0) 2(0.429,0)
FILTS-0603
  rect 0.762x0.889 smd: 1(-0.681,0) 2(0.681,0)
FILTS-PBY321611T
  rect 0.991x1.803 smd: 1(-1.5,0) 2(1.5,0)
FUSES-1206L
  rect 1.016x1.803 smd: 1(-1.4,0) 2(1.4,0)
L0402
  rect 0.508x0.508 smd: 1(-0.429,0) 2(0.429,0)
L0402-1
  rect 0.406x0.508 smd: 1(-0.4,0) 2(0.4,0)
LEDS-LTST-T180
  rect 0.406x0.508 smd: A(-0.6,0)
  rect 0.889x0.508 smd: C(0.35,0)
LRS-ATNR50XX
  rect 5.512x1.803 smd: 1(0,-1.65) 2(0,1.65)
LRS-ATNR4030
  rect 3.988x1.346 smd: 1(0,-1.325) 2(0,1.325)
LRS-ATNR6028
  rect 5.69x1.6 smd: 1(0,-2.35) 2(0,2.35)
LS-AMPI2520
  rect 0.991x2.007 smd: 1(-1.1,0) 2(1.1,0)
LS-MWSA06XXS
  rect 2.362x3.505 smd: 1(-3.025,0) 2(3.025,0)
LS-SWPA30
  rect 0.813x2.692 smd: 1(-1.15,0) 2(1.15,0)
LS-TMIM2016
  rect 0.991x1.905 smd: 1(-0.75,0) 2(0.75,0)
LS-UPIF06XXW
  rect 2.362x3.505 smd: 1(-3.025,0) 2(3.025,0)
LS-WIP2016
  rect 0.94x1.6 smd: 1(-0.925,0) 2(0.925,0)
MLCC-0120X0070
  rect 0.559x0.711 smd: 1(-0.457,0) 2(0.457,0)
OPTIC-THBD277E4S
  round 1.422 hole 0.914: 1(0,0) 8(0,-5.2) 14(0,-9.7)
  rect 1.295x0.406 smd: 2(-2.21,-0.25) 3(-2.21,-1.05) 4(-2.21,-1.85) 5(-2.21,-2.65) 6(-2.21,-3.45) 7(-2.21,-4.25) 9(-2.21,-5.95) 10(-2.21,-6.75) 11(-2.21,-7.55) 12(-2.21,-8.35) 13(-2.21,-9.15)
  round 1.753 hole 1.245: 15(19.44,-4.05) 16(19.44,-10.65) 17(11.94,-4.05)
QFN11-0200-0500
  rect 1.499x0.254 smd: 1(-0.55,0.25) 6(0.55,-0.25)
  rect 0.254x0.711 smd: 2(-0.75,-1) 3(-0.25,-1) 4(0.25,-1) 5(0.75,-1) 8(0.75,1) 9(0.25,1) 10(-0.25,1) 11(-0.75,1)
  rect 0.711x0.254 smd: 7(0.95,0.25)
QFN20-0400-0500-VIA-30
  rect 0.711x0.254 smd: 1(-1.975,1) 2(-1.975,0.5) 3(-1.975,0) 4(-1.975,-0.5) 5(-1.975,-1) 11(1.975,-1) 12(1.975,-0.5) 13(1.975,0) 14(1.975,0.5) 15(1.975,1)
  rect 0.254x0.711 smd: 6(-1,-1.975) 7(-0.5,-1.975) 8(0,-1.975) 9(0.5,-1.975) 10(1,-1.975) 16(1,1.975) 17(0.5,1.975) 18(0,1.975) 19(-0.5,1.975) 20(-1,1.975)
  rect 2.591x2.591 smd: 21(0,0)
  round 0.61 hole 0.305: 22(-0.9,0.9) 23(0,0.9) 24(0.9,0.9) 25(-0.9,0) 26(0,0) 27(0.9,0) 28(-0.9,-0.9) 29(0,-0.9) 30(0.9,-0.9)
QFN32-0400-0400-VIA-5-PH10
  custom 0.057x0.057 smd: 1(-1.925,1.4) 8(-1.925,-1.4) 9(-1.4,-1.925) 16(1.4,-1.925) 17(1.925,-1.4) 24(1.925,1.4) 25(1.4,1.925) 32(-1.4,1.925)
  rect 0.762x0.229 smd: 2(-1.925,1) 3(-1.925,0.6) 4(-1.925,0.2) 5(-1.925,-0.2) 6(-1.925,-0.6) 7(-1.925,-1) 18(1.925,-1) 19(1.925,-0.6) 20(1.925,-0.2) 21(1.925,0.2) 22(1.925,0.6) 23(1.925,1)
  rect 0.229x0.762 smd: 10(-1,-1.925) 11(-0.6,-1.925) 12(-0.2,-1.925) 13(0.2,-1.925) 14(0.6,-1.925) 15(1,-1.925) 26(1,1.925) 27(0.6,1.925) 28(0.2,1.925) 29(-0.2,1.925) 30(-0.6,1.925) 31(-1,1.925)
  rect 1.245x1.245 smd: 33(-0.725,0.725) 34(0.725,0.725) 35(-0.725,-0.725) 36(0.725,-0.725)
  round 0.508 hole 0.254: 37(-0.725,0.725) 38(0.725,0.725) 39(0.725,-0.725) 40(-0.725,-0.725)
QFN68-0800-0400-VIA-10-PH10
  rect 0.813x0.203 smd: 1(-3.9,3.2) 2(-3.9,2.8) 3(-3.9,2.4) 4(-3.9,2) 5(-3.9,1.6) 6(-3.9,1.2) 7(-3.9,0.8) 8(-3.9,0.4) 9(-3.9,0) 10(-3.9,-0.4) 11(-3.9,-0.8) 12(-3.9,-1.2) 13(-3.9,-1.6) 14(-3.9,-2) 15(-3.9,-2.4) 16(-3.9,-2.8) 17(-3.9,-3.2) 35(3.9,-3.2) 36(3.9,-2.8) 37(3.9,-2.4) 38(3.9,-2) 39(3.9,-1.6) 40(3.9,-1.2) 41(3.9,-0.8) 42(3.9,-0.4) 43(3.9,0) 44(3.9,0.4) 45(3.9,0.8) 46(3.9,1.2) 47(3.9,1.6) 48(3.9,2) 49(3.9,2.4) 50(3.9,2.8) 51(3.9,3.2)
  rect 0.203x0.813 smd: 18(-3.2,-3.9) 19(-2.8,-3.9) 20(-2.4,-3.9) 21(-2,-3.9) 22(-1.6,-3.9) 23(-1.2,-3.9) 24(-0.8,-3.9) 25(-0.4,-3.9) 26(0,-3.9) 27(0.4,-3.9) 28(0.8,-3.9) 29(1.2,-3.9) 30(1.6,-3.9) 31(2,-3.9) 32(2.4,-3.9) 33(2.8,-3.9) 34(3.2,-3.9) 52(3.2,3.9) 53(2.8,3.9) 54(2.4,3.9) 55(2,3.9) 56(1.6,3.9) 57(1.2,3.9) 58(0.8,3.9) 59(0.4,3.9) 60(0,3.9) 61(-0.4,3.9) 62(-0.8,3.9) 63(-1.2,3.9) 64(-1.6,3.9) 65(-2,3.9) 66(-2.4,3.9) 67(-2.8,3.9) 68(-3.2,3.9)
  rect 1.702x5.004 smd: 69(-1.95,0)
  rect 3.505x5.004 smd: 70(1.05,0)
  round 0.508 hole 0.254: 71(-2.5,2.1) 72(-2.5,1.5) 73(-2.5,0.9) 74(-2.5,0.3) 75(-2.5,-0.3) 76(-2.5,-0.9) 77(-2.5,-1.5) 78(-2.5,-2.1) 79(-1.95,2.1) 80(-1.95,1.5) 81(-1.95,0.9) 82(-1.95,0.3) 83(-1.95,-0.3) 84(-1.95,-0.9) 85(-1.95,-1.5) 86(-1.95,-2.1) 87(-1.4,2.1) 88(-1.4,1.5) 89(-1.4,0.9) 90(-1.4,0.3) 91(-1.4,-0.3) 92(-1.4,-0.9) 93(-1.4,-1.5) 94(-1.4,-2.1) 95(-0.325,2.1) 96(-0.325,1.5) 97(-0.325,0.9) 98(-0.325,0.3) 99(-0.325,-0.3) 100(-0.325,-0.9) 101(-0.325,-1.5) 102(-0.325,-2.1) 103(0.225,2.1) 104(0.225,1.5) 105(0.225,0.9) 106(0.225,0.3) 107(0.225,-0.3) 108(0.225,-0.9) 109(0.225,-1.5) 110(0.225,-2.1) 111(0.775,2.1) 112(0.775,1.5) 113(0.775,0.9) 114(0.775,0.3) 115(0.775,-0.3) 116(0.775,-0.9) 117(0.775,-1.5) 118(0.775,-2.1) 119(1.325,2.1) 120(1.325,1.5) 121(1.325,0.9) 122(1.325,0.3) 123(1.325,-0.3) 124(1.325,-0.9) 125(1.325,-1.5) 126(1.325,-2.1) 127(1.875,2.1) 128(1.875,1.5) 129(1.875,0.9) 130(1.875,0.3) 131(1.875,-0.3) 132(1.875,-0.9) 133(1.875,-1.5) 134(1.875,-2.1) 135(2.425,2.1) 136(2.425,1.5) 137(2.425,0.9) 138(2.425,0.3) 139(2.425,-0.3) 140(2.425,-0.9) 141(2.425,-1.5) 142(2.425,-2.1)
QFN144-1100-0500-PAD
  rect 0.508x0.229 smd: 1(-5.35,4.75) 2(-5.35,4.25) 3(-4.6,4) 4(-5.35,3.75) 5(-4.6,3.5) 6(-5.35,3.25) 7(-4.6,3) 8(-5.35,2.75) 9(-4.6,2.5) 10(-5.35,2.25) 11(-4.6,2) 12(-5.35,1.75) 13(-4.6,1.5) 14(-5.35,1.25) 15(-4.6,1) 16(-5.35,0.75) 17(-4.6,0.5) 18(-5.35,0.25) 19(-4.6,0) 20(-5.35,-0.25) 21(-4.6,-0.5) 22(-5.35,-0.75) 23(-4.6,-1) 24(-5.35,-1.25) 25(-4.6,-1.5) 26(-5.35,-1.75) 27(-4.6,-2) 28(-5.35,-2.25) 29(-4.6,-2.5) 30(-5.35,-2.75) 31(-4.6,-3) 32(-5.35,-3.25) 33(-4.6,-3.5) 34(-5.35,-3.75) 35(-4.6,-4) 36(-5.35,-4.25) 74(5.35,-4.25) 75(4.6,-4) 76(5.35,-3.75) 77(4.6,-3.5) 78(5.35,-3.25) 79(4.6,-3) 80(5.35,-2.75) 81(4.6,-2.5) 82(5.35,-2.25) 83(4.6,-2) 84(5.35,-1.75) 85(4.6,-1.5) 86(5.35,-1.25) 87(4.6,-1) 88(5.35,-0.75) 89(4.6,-0.5) 90(5.35,-0.25) 91(4.6,0) 92(5.35,0.25) 93(4.6,0.5) 94(5.35,0.75) 95(4.6,1) 96(5.35,1.25) 97(4.6,1.5) 98(5.35,1.75) 99(4.6,2) 100(5.35,2.25) 101(4.6,2.5) 102(5.35,2.75) 103(4.6,3) 104(5.35,3.25) 105(4.6,3.5) 106(5.35,3.75) 107(4.6,4) 108(5.35,4.25)
  rect 0.229x0.508 smd: 37(-4.75,-5.35) 38(-4.25,-5.35) 39(-4,-4.6) 40(-3.75,-5.35) 41(-3.5,-4.6) 42(-3.25,-5.35) 43(-3,-4.6) 44(-2.75,-5.35) 45(-2.5,-4.6) 46(-2.25,-5.35) 47(-2,-4.6) 48(-1.75,-5.35) 49(-1.5,-4.6) 50(-1.25,-5.35) 51(-1,-4.6) 52(-0.75,-5.35) 53(-0.5,-4.6) 54(-0.25,-5.35) 55(0,-4.6) 56(0.25,-5.35) 57(0.5,-4.6) 58(0.75,-5.35) 59(1,-4.6) 60(1.25,-5.35) 61(1.5,-4.6) 62(1.75,-5.35) 63(2,-4.6) 64(2.25,-5.35) 65(2.5,-4.6) 66(2.75,-5.35) 67(3,-4.6) 68(3.25,-5.35) 69(3.5,-4.6) 70(3.75,-5.35) 71(4,-4.6) 72(4.25,-5.35) 73(4.75,-5.35) 109(4.75,5.35) 110(4.25,5.35) 111(4,4.6) 112(3.75,5.35) 113(3.5,4.6) 114(3.25,5.35) 115(3,4.6) 116(2.75,5.35) 117(2.5,4.6) 118(2.25,5.35) 119(2,4.6) 120(1.75,5.35) 121(1.5,4.6) 122(1.25,5.35) 123(1,4.6) 124(0.75,5.35) 125(0.5,4.6) 126(0.25,5.35) 127(0,4.6) 128(-0.25,5.35) 129(-0.5,4.6) 130(-0.75,5.35) 131(-1,4.6) 132(-1.25,5.35) 133(-1.5,4.6) 134(-1.75,5.35) 135(-2,4.6) 136(-2.25,5.35) 137(-2.5,4.6) 138(-2.75,5.35) 139(-3,4.6) 140(-3.25,5.35) 141(-3.5,4.6) 142(-3.75,5.35) 143(-4,4.6) 144(-4.25,5.35)
  rect 5.893x6.604 smd: 145(0,-0.15)
R0201
  rect 0.305x0.305 smd: 1(-0.246,0) 2(0.246,0)
R0402
  rect 0.508x0.508 smd: 1(-0.429,0) 2(0.429,0)
R0603
  rect 0.762x0.889 smd: 1(-0.681,0) 2(0.681,0)
R0805
  rect 0.991x1.397 smd: 1(-0.795,0) 2(0.795,0)
R1206
  rect 1.245x1.753 smd: 1(-1.212,0) 2(1.212,0)
RJ45-ZW2J88-J260S1X
  round 3.251 hole 3.251 unplated: (-6.35,0) (6.35,0)
  rect 1.372x1.372 hole 0.864: 1(3.57,2.54)
  round 1.372 hole 0.864: 2(2.55,4.32) 3(1.53,2.54) 4(0.51,4.32) 5(-0.51,2.54) 6(-1.53,4.32) 7(-2.55,2.54) 8(-3.57,4.32)
  round 2.311 hole 1.803: G1(8.1,3.56) G2(-8.1,3.56)
SHIELD-02340X02320-0300-1
  oval 1.727x1.118 hole 1.219x0.61: 1(6.5,11.6) 3(-3.7,-11.6)
  oval 1.118x1.727 hole 0.61x1.219: 2(11.5,-1.8) 4(-11.5,-1.2)
SHIELD-04250X03180-0200-1
  oval 1.727x1.118 hole 1.219x0.61: 1(-1.15,15.75) 3(-14.35,-15.75)
  oval 1.118x1.727 hole 0.61x1.219: 2(21.1,10.4)
SHIELD-04430X02373-TEST
  oval 1.118x1.727 hole 0.61x1.219: 1(-10.215,17.055)
  oval 1.727x1.118 hole 1.219x0.61: 2(7.085,-22)
SHIELD-05460X02020-0995
  oval 1.118x1.727 hole 0.61x1.219: 1(9.95,6.75) 3(-9.95,-7.35)
  oval 1.727x1.118 hole 1.219x0.61: 2(-0.65,-27.15)
SHIELD-COVER
  round 0.254 smd: 1(0,0)
SIP4-PHE6T0-104L4
  rect 1.549x1.549 hole 1.041: 1(-3.81,0)
  round 1.549 hole 1.041: 2(-1.27,0) 3(1.27,0) 4(3.81,0)
SIP5-02040-01G059
  rect 1.549x1.549 hole 1.041: 1(-5.08,0)
  round 1.549 hole 1.041: 2(-2.54,0) 3(0,0) 5(5.08,0)
SON8-0330-0650-PAD-3
  rect 0.61x0.406 smd: 1(-1.475,0.975) 2(-1.475,0.325) 3(-1.475,-0.325) 4(-1.475,-0.975)
  custom 0.65x0.65 smd: 5(1.475,-0.975)
  rect 0.584x0.381 smd: 6(1.475,-0.325) 7(1.475,0.325) 8(1.475,0.975)
SON8-0800-1270-VIA-3
  rect 0.813x0.483 smd: 1(-3.9,1.905) 2(-3.9,0.635) 3(-3.9,-0.635) 4(-3.9,-1.905) 5(3.9,-1.905) 6(3.9,-0.635) 7(3.9,0.635) 8(3.9,1.905)
  rect 3.404x4.293 smd: 9(0,0)
  round 0.559 hole 0.254: 10(-1.4,1.75) 11(-0.7,1.75) 12(0,1.75) 13(0.7,1.75) 14(1.4,1.75) 15(-1.4,1.05) 16(-0.7,1.05) 17(0,1.05) 18(0.7,1.05) 19(1.4,1.05) 20(-1.4,0.35) 21(-0.7,0.35) 22(0,0.35) 23(0.7,0.35) 24(1.4,0.35) 25(-1.4,-0.35) 26(-0.7,-0.35) 27(0,-0.35) 28(0.7,-0.35) 29(1.4,-0.35) 30(-1.4,-1.05) 31(-0.7,-1.05) 32(0,-1.05) 33(0.7,-1.05) 34(1.4,-1.05) 35(-1.4,-1.75) 36(-0.7,-1.75) 37(0,-1.75) 38(0.7,-1.75) 39(1.4,-1.75)
SON10-0200-0400-VIA-1
  custom 0.051x0.051 smd: 1(-0.8,-0.95) 2(-0.4,-0.95) 3(0,-0.95) 4(0.4,-0.95) 5(0.8,-0.95) 6(0.8,0.95) 7(0.4,0.95) 8(0,0.95) 9(-0.4,0.95) 10(-0.8,0.95)
  custom 0.21x0.21 smd: 11(0,0)
  round 0.356 hole 0.203: 12(-0.5,0) 13(0.5,0)
SOP4-0700-1270
  oval 0.508x1.524 smd: 1(-0.635,-3.24) 2(0.635,-3.24) 3(0.635,3.24) 4(-0.635,3.24)
SOP8-0600-1270
  oval 0.559x1.524 smd: 1(-1.905,-2.738) 2(-0.635,-2.738) 3(0.635,-2.738) 4(1.905,-2.738) 5(1.905,2.738) 6(0.635,2.738) 7(-0.635,2.738) 8(-1.905,2.738)
SOP8-0600-1270-9
  rect 0.61x1.524 smd: 1(-1.905,-2.76) 2(-0.635,-2.76) 3(0.635,-2.76) 4(1.905,-2.76) 5(1.905,2.76) 6(0.635,2.76) 7(-0.635,2.76) 8(-1.905,2.76)
SOP8-0600-1270-VIA-2
  rect 0.61x1.6 smd: 1(-1.905,-2.7) 2(-0.635,-2.7) 3(0.635,-2.7) 4(1.905,-2.7) 5(1.905,2.7) 6(0.635,2.7) 7(-0.635,2.7) 8(-1.905,2.7)
  rect 3.505x2.616 smd: 9(0,0)
  round 0.61 hole 0.305: 10(-1.2,0.8) 11(-1.2,-0.8) 12(0,0.8) 13(0,-0.8) 14(1.2,0.8) 15(1.2,-0.8)
SOP8-0640-0650
  oval 0.381x1.524 smd: 1(-0.975,-2.925) 2(-0.325,-2.925) 3(0.325,-2.925) 4(0.975,-2.925) 5(0.975,2.925) 6(0.325,2.925) 7(-0.325,2.925) 8(-0.975,2.925)
SOP8-0790-1270
  oval 0.559x1.524 smd: 1(-1.905,-3.688) 2(-0.635,-3.688) 3(0.635,-3.688) 4(1.905,-3.688) 5(1.905,3.688) 6(0.635,3.688) 7(-0.635,3.688) 8(-1.905,3.688)
SOP10-0490-0500-3
  rect 0.305x1.016 smd: 1(-1,-2.3) 2(-0.5,-2.3) 3(0,-2.3) 4(0.5,-2.3) 5(1,-2.3) 6(1,2.3) 7(0.5,2.3) 8(0,2.3) 9(-0.5,2.3) 10(-1,2.3)
SOP28-0640-0650-3
  rect 0.305x1.6 smd: 1(-4.225,-2.8) 2(-3.575,-2.8) 3(-2.925,-2.8) 4(-2.275,-2.8) 5(-1.625,-2.8) 6(-0.975,-2.8) 7(-0.325,-2.8) 8(0.325,-2.8) 9(0.975,-2.8) 10(1.625,-2.8) 11(2.275,-2.8) 12(2.925,-2.8) 13(3.575,-2.8) 14(4.225,-2.8) 15(4.225,2.8) 16(3.575,2.8) 17(2.925,2.8) 18(2.275,2.8) 19(1.625,2.8) 20(0.975,2.8) 21(0.325,2.8) 22(-0.325,2.8) 23(-0.975,2.8) 24(-1.625,2.8) 25(-2.275,2.8) 26(-2.925,2.8) 27(-3.575,2.8) 28(-4.225,2.8)
SOT-23-5-RICHTEK
  rect 0.711x0.991 smd: 1(-0.95,-1.3) 2(0,-1.3) 3(0.95,-1.3) 4(0.95,1.3) 5(-0.95,1.3)
SOT-23-5-TI-1
  custom 0.152x0.152 smd: 1(-0.95,-1.3) 2(0,-1.3) 3(0.95,-1.3) 4(0.95,1.3) 5(-0.95,1.3)
SOT-23-EBC
  rect 0.762x1.397 smd: B(-0.95,-1.05) C(0,1.05) E(0.95,-1.05)
SOT-23-RGV
  rect 0.762x1.397 smd: GND(-0.95,-1.05) RST(0.95,-1.05) VCC(0,1.05)
SOT-23-SGD
  rect 0.762x1.397 smd: D(0,1.05) G(-0.955,-1.05) S(0.955,-1.05)
SOT-89-3L-RAC-TI
  custom 0.55x0.55 smd: A(0,-2)
  rect 0.991x1.499 smd: C(1.5,-2) REF(-1.5,-2)
SOT-363-LRC
  rect 0.406x0.508 smd: 1(-0.65,-0.95) 2(0,-0.95) 3(0.65,-0.95) 4(0.65,0.95) 5(0,0.95) 6(-0.65,0.95)
SOT-583-MPS
  rect 0.254x0.61 smd: 1(-0.75,-0.7) 2(-0.25,-0.7) 3(0.25,-0.7) 4(0.75,-0.7) 5(0.75,0.7) 6(0.25,0.7) 7(-0.25,0.7) 8(-0.75,0.7)
SW-KAN0631-0501B
  rect 1.524x1.524 hole 1.016: 1(-2.25,0)
  round 1.524 hole 1.016: 2(2.25,0)
  round 1.829 hole 1.321: 3(-3.5,2.5) 4(3.5,2.5)
TO-252-GDS-SECOS
  rect 7.01x7.01 smd: D(0,1.6)
  rect 1.499x2.489 smd: G(-2.3,-5.3) S(2.3,-5.3)
TP13
  round 0.508 smd: 1(0,0)
TRS12-PL9954
  rect 1.651x2.515 smd: 1(-9.375,-15.365) 2(-5.625,-15.365) 3(-1.875,-15.365) 4(1.875,-15.365) 5(5.625,-15.365) 6(9.375,-15.365) 7(9.375,15.365) 8(5.625,15.365) 9(1.875,15.365) 10(-1.875,15.365) 11(-5.625,15.365) 12(-9.375,15.365)
TRS24-UTG24C
  rect 0.762x2.54 smd: 1(-6.985,-7.23) 2(-5.715,-7.23) 3(-4.445,-7.23) 4(-3.175,-7.23) 5(-1.905,-7.23) 6(-0.635,-7.23) 7(0.635,-7.23) 8(1.905,-7.23) 9(3.175,-7.23) 10(4.445,-7.23) 11(5.715,-7.23) 12(6.985,-7.23) 13(6.985,7.23) 14(5.715,7.23) 15(4.445,7.23) 16(3.175,7.23) 17(1.905,7.23) 18(0.635,7.23) 19(-0.635,7.23) 20(-1.905,7.23) 21(-3.175,7.23) 22(-4.445,7.23) 23(-5.715,7.23) 24(-6.985,7.23)
TRS24-UTTG24CXX
  rect 0.762x2.54 smd: 1(-6.985,-7.23) 2(-5.715,-7.23) 3(-4.445,-7.23) 4(-3.175,-7.23) 5(-1.905,-7.23) 6(-0.635,-7.23) 7(0.635,-7.23) 8(1.905,-7.23) 9(3.175,-7.23) 10(4.445,-7.23) 11(5.715,-7.23) 12(6.985,-7.23) 13(6.985,7.23) 14(5.715,7.23) 15(4.445,7.23) 16(3.175,7.23) 17(1.905,7.23) 18(0.635,7.23) 19(-0.635,7.23) 20(-1.905,7.23) 21(-3.175,7.23) 22(-4.445,7.23) 23(-5.715,7.23) 24(-6.985,7.23)
TRS48-UTV48C
  rect 0.635x2.54 smd: 1(-11.73,-7.33) 2(-10.71,-7.33) 3(-9.69,-7.33) 4(-8.67,-7.33) 5(-7.65,-7.33) 6(-6.63,-7.33) 7(-5.61,-7.33) 8(-4.59,-7.33) 9(-3.57,-7.33) 10(-2.55,-7.33) 11(-1.53,-7.33) 12(-0.51,-7.33) 13(0.51,-7.33) 14(1.53,-7.33) 15(2.55,-7.33) 16(3.57,-7.33) 17(4.59,-7.33) 18(5.61,-7.33) 19(6.63,-7.33) 20(7.65,-7.33) 21(8.67,-7.33) 22(9.69,-7.33) 23(10.71,-7.33) 24(11.73,-7.33) 25(11.73,7.33) 26(10.71,7.33) 27(9.69,7.33) 28(8.67,7.33) 29(7.65,7.33) 30(6.63,7.33) 31(5.61,7.33) 32(4.59,7.33) 33(3.57,7.33) 34(2.55,7.33) 35(1.53,7.33) 36(0.51,7.33) 37(-0.51,7.33) 38(-1.53,7.33) 39(-2.55,7.33) 40(-3.57,7.33) 41(-4.59,7.33) 42(-5.61,7.33) 43(-6.63,7.33) 44(-7.65,7.33) 45(-8.67,7.33) 46(-9.69,7.33) 47(-10.71,7.33) 48(-11.73,7.33)
unnamed#2
  round 1.016 smd: (0,0)
VARS-BZXXN
  rect 1.245x2.794 smd: 1(-1.625,0) 2(1.625,0)
VARS-DFN1006P2E-AMAZING
  rect 0.559x0.61 smd: 1(-0.425,0) 2(0.425,0)
VARS-DFN1610-6L-YANGJIE
  rect 0.203x0.686 smd: 1(-0.55,-0.435) 2(-0.05,-0.435) 5(-0.05,0.435) 6(-0.55,0.435)
  rect 0.406x0.787 smd: 3(0.45,-0.381) 4(0.45,0.381)
VARS-SMB-BENCENT
  rect 2.159x2.743 smd: 1(-2.21,0) 2(2.21,0)
VARS-SMB-PANJIT
  rect 2.286x2.718 smd: 1(-2.025,0) 2(2.025,0)
VARS-SOD-323-BENCENT
  rect 1.067x0.533 smd: 1(-1.07,0) 2(1.07,0)
VARS-SOD-323-PANJIT
  rect 0.737x0.508 smd: 1(-1.085,0) 2(1.085,0)
VIA217P-393P
  round 9.982 hole 5.512: 1(0,0)
XTALS-0320X0250-3
  rect 1.397x1.194 smd: 1(-1.1,-0.85) 2(1.1,-0.85) 3(1.1,0.85) 4(-1.1,0.85)
XTALS-0320X0250-YOKE
  rect 1.295x1.041 smd: 1(-1.15,-0.925) 2(1.15,-0.925) 3(1.15,0.925) 4(-1.15,0.925)

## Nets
0V9_PG: PR383.1 PU10.5 R975.1
1V9_PG: PC385.1 PC485.1 PR463.2 PR465.1 PR467.1 PU15.6 PU16.1
1V35_PG: PC358.1 PC430.1 PR352.1 PR380.2 PR462.1 PU10.11 PU14.1
3V3_PG: PC486.1 PC487.1 PR466.2 PR468.1 PR469.2 PR471.1 PR610.1 PU16.6 PU17.6 PU40.5
AVDDH_PHY0: E1C39.1 E1C40.1 E1C41.1 E1C42.2 E1C43.2 E1C44.2 E1C45.1 E1C46.1 E1C47.2 E1LP1.2 E1U1.1 E1U1.7 E1U1.14
AVDDH_PLL0: E1C81.1 E1C82.2 E1C83.1 E1FB1.2 E1U1.64
AVDDL_PHY0: E1C59.1 E1C60.1 E1C61.2 E1C62.2 E1C63.2 E1C64.1 E1C65.2 E1L3.2 E1U1.8 E1U1.13
AVDDL_PLL0: E1C76.1 E1C77.2 E1C78.2 E1L4.2 E1U1.63
